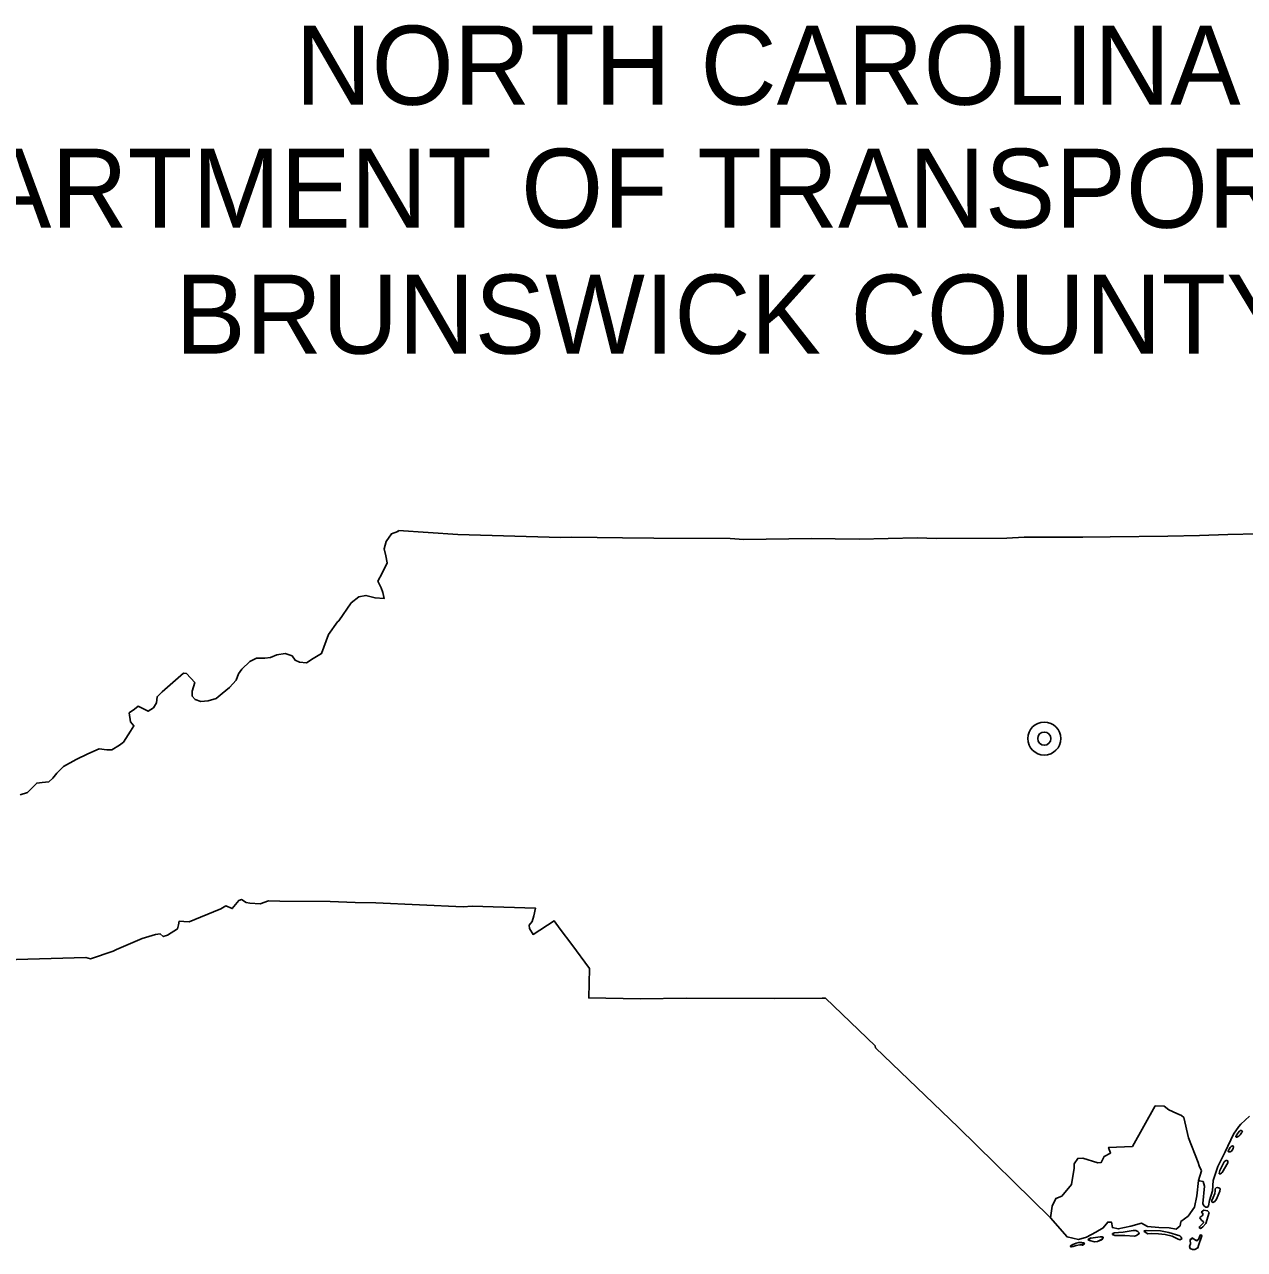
# Model space of a CAD drawing. Extents: x 0 to 3.05, y 0 to 1.83.
# Drawn here: x 2.6292 to 2.7218, y 1.6092 to 1.7022 of the extents above; entities that cross this region are included whole.
import ezdxf

# ---------------------------------------------------------------- set-up
doc = ezdxf.new("R2010")
doc.units = 0
doc.layers.add('P_RDY_Dimension_Text', color=7, linetype='Continuous')
doc.layers.add('Sheet_Plan_CELL', color=7, linetype='Continuous')

msp = doc.modelspace()

# ---------------------------------------------------------------- linework, layer by layer
at = {"layer": 'P_RDY_Dimension_Text'}
for points in [[(2.71855, 1.615228), (2.718328, 1.614481), (2.718214, 1.613313), (2.718021, 1.612473), (2.717536, 1.611773), (2.716991, 1.611374), (2.716934, 1.611048), (2.716639, 1.610785), (2.716094, 1.6109), (2.715306, 1.610922), (2.714459, 1.610998), (2.714006, 1.611253), (2.713198, 1.611031), (2.712234, 1.610813), (2.711798, 1.610908), (2.711733, 1.611321), (2.711439, 1.611326), (2.711094, 1.610891), (2.71054, 1.610559), (2.709821, 1.610187), (2.709228, 1.610017), (2.708356, 1.610206), (2.707087, 1.611665), (2.707211, 1.612539), (2.707489, 1.613119), (2.707948, 1.61329), (2.708686, 1.614175), (2.708896, 1.615417), (2.708885, 1.615755), (2.709158, 1.616158), (2.709548, 1.616183), (2.710691, 1.615836), (2.710945, 1.615862), (2.711159, 1.616319), (2.711656, 1.616572), (2.711503, 1.617002), (2.71331, 1.61708), (2.715046, 1.620155), (2.715725, 1.62013), (2.716085, 1.619845), (2.716695, 1.619561), (2.717033, 1.619414), (2.717213, 1.619271), (2.71758, 1.617726), (2.718296, 1.615854), (2.718386, 1.615592)], [(2.711903, 1.610504), (2.712604, 1.610559), (2.713379, 1.61069), (2.713572, 1.610701), (2.713733, 1.610615), (2.713822, 1.610507), (2.713619, 1.610302), (2.713481, 1.610263), (2.712728, 1.610304), (2.712186, 1.610318), (2.711964, 1.61032), (2.711841, 1.610356)], [(2.714355, 1.610689), (2.715431, 1.610677), (2.716088, 1.610551), (2.716906, 1.610275), (2.717025, 1.610193), (2.71706, 1.61005), (2.71691, 1.609981), (2.716741, 1.610055), (2.716335, 1.610268), (2.715787, 1.610387), (2.715299, 1.61044), (2.714762, 1.610459), (2.714476, 1.610447), (2.714205, 1.61062)], [(2.708591, 1.609512), (2.708738, 1.60961), (2.709033, 1.609731), (2.709234, 1.609782), (2.709362, 1.609792), (2.709471, 1.609778), (2.709596, 1.609744), (2.709516, 1.609588), (2.70932, 1.609598), (2.70905, 1.609546), (2.70882, 1.609484)], [(2.71005, 1.609924), (2.709998, 1.610003), (2.710157, 1.610111), (2.710874, 1.610204), (2.711017, 1.610201), (2.711061, 1.610067), (2.710656, 1.609865), (2.710421, 1.609832)], [(2.717883, 1.610115), (2.718154, 1.609925), (2.718321, 1.61002), (2.718451, 1.610341), (2.718586, 1.610275), (2.718335, 1.609541), (2.718278, 1.609364), (2.718061, 1.60926), (2.717877, 1.60925), (2.717708, 1.609315), (2.717655, 1.609482), (2.71772, 1.609685), (2.7177, 1.60997)]]:
    msp.add_lwpolyline(points, close=True, dxfattribs=at)
for radius in [0.001254, 0.0005]:
    msp.add_circle((2.706623, 1.64803), radius, dxfattribs=at)
at = {"layer": 'Sheet_Plan_CELL'}
for points in [[(2.727468, 1.663682), (2.720547, 1.663529), (2.718403, 1.663459), (2.716004, 1.663406), (2.711617, 1.663359), (2.709553, 1.663333), (2.705105, 1.663324), (2.703781, 1.663239), (2.698446, 1.663216), (2.696981, 1.663263), (2.692572, 1.663166), (2.688935, 1.663216), (2.683812, 1.663157), (2.682771, 1.66322), (2.676986, 1.663236), (2.67459, 1.663281), (2.670746, 1.663318), (2.669904, 1.663298), (2.662101, 1.663516), (2.657598, 1.663816), (2.657543, 1.663754), (2.657051, 1.663567), (2.656649, 1.663), (2.656504, 1.662446), (2.65664, 1.661902), (2.65673, 1.661363), (2.656347, 1.660589), (2.656034, 1.659989), (2.656267, 1.659478), (2.656404, 1.659118), (2.656507, 1.65867), (2.655816, 1.658714), (2.65512, 1.658896), (2.654571, 1.658784), (2.654, 1.658332), (2.653054, 1.65697), (2.652973, 1.656889), (2.65229, 1.655926), (2.651753, 1.65449), (2.651125, 1.654114), (2.65062, 1.653791), (2.650071, 1.653838), (2.649744, 1.653993), (2.649509, 1.654319), (2.649, 1.654497), (2.648362, 1.654395), (2.647871, 1.654183), (2.64745, 1.654144), (2.646823, 1.654131), (2.646305, 1.653877), (2.645701, 1.653314), (2.645448, 1.652958), (2.645271, 1.652479), (2.64476, 1.651905), (2.644194, 1.651452), (2.643754, 1.651074), (2.643132, 1.6509), (2.642595, 1.650851), (2.642151, 1.650996), (2.641929, 1.65125), (2.641931, 1.651637), (2.642129, 1.652295), (2.641496, 1.652963), (2.641268, 1.652991), (2.63964, 1.651594), (2.639269, 1.651207), (2.639214, 1.650759), (2.638983, 1.650378), (2.63858, 1.650108), (2.63782, 1.650493), (2.63754, 1.650276), (2.637136, 1.649984), (2.637239, 1.649313), (2.637501, 1.64901), (2.637242, 1.648587), (2.636728, 1.647763), (2.6364, 1.647529)], [(2.6364, 1.647529), (2.63583, 1.647188), (2.635438, 1.647189), (2.634871, 1.647255), (2.633998, 1.646881), (2.633117, 1.646439), (2.632158, 1.645915), (2.631662, 1.645406), (2.631342, 1.645035), (2.631056, 1.644751), (2.630544, 1.644696), (2.630126, 1.644654), (2.629787, 1.644307), (2.629423, 1.643942), (2.628873, 1.643755)], [(2.627701, 1.631228), (2.633845, 1.631403), (2.634222, 1.631314), (2.635932, 1.631901), (2.636175, 1.632029), (2.638144, 1.632853), (2.63914, 1.633162), (2.639488, 1.63321), (2.639736, 1.633), (2.640047, 1.633121), (2.640812, 1.633591), (2.640895, 1.633896), (2.640954, 1.634181), (2.641291, 1.63414), (2.641698, 1.634114), (2.642566, 1.634481), (2.644106, 1.635103), (2.644477, 1.635328), (2.644977, 1.635131), (2.645467, 1.635747), (2.645681, 1.63581), (2.64604, 1.635586), (2.64631, 1.635552), (2.647103, 1.635499), (2.647725, 1.635714), (2.648592, 1.635696), (2.652406, 1.635663), (2.654292, 1.635578), (2.655867, 1.635554), (2.662506, 1.635262), (2.663176, 1.635307), (2.667985, 1.635169), (2.667878, 1.634575), (2.667748, 1.634142), (2.667524, 1.633857), (2.667535, 1.633608), (2.667815, 1.633163), (2.669404, 1.634206), (2.669859, 1.633556), (2.670744, 1.632396), (2.672104, 1.630583), (2.672031, 1.628344), (2.675943, 1.628283), (2.679462, 1.628337), (2.686166, 1.628314), (2.689752, 1.628335), (2.690023, 1.628316), (2.693784, 1.6247), (2.693808, 1.624562), (2.700088, 1.618525), (2.707087, 1.611665), (2.708356, 1.610206)], [(2.640047, 1.633121), (2.639736, 1.633), (2.639488, 1.63321), (2.63914, 1.633162), (2.638144, 1.632853), (2.636175, 1.632029), (2.635932, 1.631901)], [(2.708356, 1.610206), (2.709228, 1.610017), (2.709821, 1.610187), (2.71054, 1.610559), (2.711094, 1.610891), (2.711439, 1.611326), (2.711733, 1.611321), (2.711798, 1.610908), (2.712234, 1.610813), (2.713198, 1.611031), (2.714006, 1.611253), (2.714459, 1.610998), (2.715306, 1.610922), (2.716094, 1.6109), (2.716639, 1.610785), (2.716934, 1.611048), (2.716991, 1.611374), (2.717536, 1.611773), (2.718021, 1.612473), (2.718214, 1.613313), (2.718328, 1.614481), (2.718394, 1.61447), (2.718676, 1.614399), (2.718773, 1.614046), (2.718658, 1.612745), (2.718728, 1.612574), (2.718876, 1.612469), (2.719023, 1.612471), (2.719088, 1.612566), (2.719173, 1.61297), (2.719391, 1.613694), (2.719441, 1.614492), (2.719787, 1.615553), (2.720347, 1.616668), (2.720991, 1.617994), (2.721394, 1.618598), (2.72154, 1.618775), (2.722194, 1.61938)], [(2.721186, 1.617886), (2.72131, 1.618092), (2.72144, 1.618232), (2.721519, 1.61829), (2.721578, 1.618295), (2.721629, 1.61825), (2.721659, 1.618187), (2.721593, 1.618113), (2.721481, 1.617964), (2.721384, 1.617864), (2.721236, 1.617785), (2.721192, 1.617784), (2.721162, 1.617805), (2.721149, 1.61783), (2.721186, 1.617886)], [(2.720578, 1.616721), (2.720647, 1.616871), (2.720734, 1.616996), (2.720815, 1.617062), (2.720913, 1.617114), (2.72097, 1.617098), (2.720992, 1.617047), (2.720955, 1.616929), (2.720892, 1.616788), (2.720824, 1.616722), (2.720732, 1.616662), (2.720612, 1.616673), (2.720582, 1.616687), (2.720576, 1.616731)], [(2.71992, 1.615143), (2.719905, 1.614998), (2.71993, 1.614986), (2.719989, 1.614995), (2.720072, 1.615042), (2.720122, 1.615106), (2.72055, 1.615825), (2.720565, 1.61592), (2.720548, 1.615971), (2.720484, 1.616014), (2.720424, 1.616013), (2.720334, 1.615962), (2.72028, 1.615896), (2.719948, 1.615245), (2.719919, 1.615144)], [(2.719572, 1.613489), (2.719582, 1.613695), (2.719597, 1.613847), (2.719667, 1.613923), (2.719767, 1.613967), (2.719864, 1.613938), (2.719962, 1.613864), (2.71996, 1.613675), (2.719703, 1.613067), (2.719558, 1.612893), (2.719429, 1.612828), (2.719349, 1.612865), (2.719339, 1.612965), (2.719441, 1.613185), (2.719576, 1.613502)], [(2.71868, 1.611938), (2.718596, 1.6118), (2.718459, 1.611704), (2.718438, 1.611661), (2.718447, 1.611607), (2.718594, 1.611451), (2.718673, 1.611387), (2.718705, 1.611362), (2.718704, 1.611278), (2.718407, 1.610968), (2.718383, 1.610923), (2.718469, 1.610853), (2.71853, 1.610873), (2.718668, 1.610958), (2.718893, 1.611226), (2.719138, 1.612068)], [(2.719138, 1.612068), (2.719015, 1.612188), (2.718725, 1.612231), (2.718629, 1.612171), (2.718563, 1.612115), (2.71858, 1.612057), (2.71868, 1.611938)], [(2.711903, 1.610504), (2.712604, 1.610559), (2.713379, 1.61069), (2.713572, 1.610701), (2.713733, 1.610615), (2.713822, 1.610507), (2.713802, 1.610435), (2.713619, 1.610302), (2.713481, 1.610263), (2.712728, 1.610304), (2.712186, 1.610318), (2.711964, 1.61032), (2.711841, 1.610356), (2.711795, 1.610397), (2.711794, 1.610427), (2.711802, 1.610452), (2.7119, 1.610494)], [(2.714205, 1.61062), (2.714476, 1.610447), (2.714762, 1.610459), (2.715299, 1.61044), (2.715787, 1.610387), (2.716335, 1.610268), (2.716741, 1.610055), (2.71691, 1.609981), (2.71706, 1.61005), (2.717025, 1.610193), (2.716906, 1.610275), (2.716088, 1.610551), (2.715431, 1.610677), (2.714355, 1.610689), (2.714204, 1.61067), (2.714213, 1.61062)], [(2.708591, 1.609512), (2.708738, 1.60961), (2.709033, 1.609731), (2.709234, 1.609782), (2.709362, 1.609792), (2.709471, 1.609778), (2.709596, 1.609744), (2.709653, 1.60972), (2.709668, 1.609688), (2.709658, 1.609665), (2.709516, 1.609588), (2.709482, 1.6096), (2.709452, 1.609625), (2.70932, 1.609598), (2.70905, 1.609546), (2.70882, 1.609484), (2.708686, 1.609449), (2.708635, 1.609444), (2.708606, 1.609476), (2.708591, 1.609512)], [(2.710157, 1.610111), (2.710874, 1.610204), (2.711017, 1.610201), (2.711085, 1.610177), (2.711061, 1.610067), (2.710961, 1.609986), (2.710656, 1.609865), (2.710421, 1.609832), (2.71005, 1.609924), (2.709953, 1.609974), (2.710015, 1.610054), (2.710174, 1.610123)], [(2.717883, 1.610115), (2.718154, 1.609925), (2.718221, 1.609901), (2.718321, 1.61002), (2.718451, 1.610341), (2.718526, 1.610375), (2.718586, 1.610275), (2.718335, 1.609541), (2.718278, 1.609364), (2.718061, 1.60926), (2.717877, 1.60925), (2.717708, 1.609315), (2.717655, 1.609482), (2.71772, 1.609685), (2.7177, 1.60997), (2.717724, 1.610029), (2.717866, 1.610123), (2.717908, 1.610116)]]:
    msp.add_lwpolyline(points, dxfattribs=at)

# ---------------------------------------------------------------- texts
for s, p in [('NORTH CAROLINA', (2.649757, 1.696149)), ('DEPARTMENT OF TRANSPORTATION', (2.609394, 1.686812)), ('BRUNSWICK COUNTY', (2.640641, 1.677251))]:
    msp.add_text(s, height=0.006, rotation=0, dxfattribs=at).set_placement(p)

doc.saveas('drawing.dxf')
